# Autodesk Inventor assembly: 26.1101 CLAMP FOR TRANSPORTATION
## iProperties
Created: 2012-10
Part Number: 26.1101 CLAMP FOR TRANSPORTATION
Document SubType Name: Assembly
Designer: Administrator
Author: Administrator
